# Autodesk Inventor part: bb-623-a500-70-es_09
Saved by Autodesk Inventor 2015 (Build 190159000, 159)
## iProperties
Created: 2022-04
Part Number: bb-623-a500-70-es_09
Checked By: TraceParts S.A.
Material: Generic
Catalog Web Link: www.traceparts.com
Document SubType Name: Modeling
Designer: TraceParts
Density: 1 g/cm^3
Appearance: Default
Company: TraceParts S.A.
Author: TraceParts
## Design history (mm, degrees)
feature "bb-623-a500-70-es_09.ipt"
body "Solid1"
